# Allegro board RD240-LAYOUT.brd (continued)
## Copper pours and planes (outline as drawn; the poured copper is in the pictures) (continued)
SIG0053 on BOTTOM: 232.38,115.85 231.82,116.4 232.38,116.95 232.75,116.95 232.89,116.93 233.61,116.55 234.54,116.55 234.67,116.68 234.45,117.09 234.4,117.2 234.39,117.31 234.39,117.7 234.85,118.16 235.31,117.7 235.31,117.31 235.3,117.2 235.25,117.09 234.98,116.58 234.96,116.54 234.71,116.29 234.67,116.27 234.63,116.25 234.6,116.25 233.61,116.25 232.89,115.87 232.75,115.85
SIG0053 on BOTTOM: 236.44,115.72 236.4,115.74 236.34,115.82 236.35,115.93 236.37,115.96 236.4,115.99 236.68,116.17 237.35,116.83 237.12,117.15 237.09,117.31 237.09,118.09 237.1,118.18 237.12,118.26 237.28,118.66 237.1,119.28 237.09,119.34 237.09,120.44 237.16,120.68 237.36,120.85 237.89,121.1 238.06,121.43 238.08,121.46 238.11,121.48 238.24,121.5 238.33,121.39 238.34,121.37 238.34,121.34 238.37,121.34 238.4,121.33 238.48,121.28 238.51,121.19 238.49,121.11 238.43,121.06 238.11,120.89 238.01,120.39 238.01,119.34 238,119.28 237.82,118.66 237.98,118.26 238,118.18 238.01,118.09 238.01,117.31 237.98,117.15 237.67,116.73 237.66,116.72 236.9,115.96 236.71,115.68 236.69,115.65 236.57,115.61 236.46,115.68
SIG0053 on BOTTOM: 233.23,118.44 233.04,118.36 232.96,118.55 232.96,118.57 233.18,119.03 233.18,119.12 233.19,119.18 234.09,120.11 234.13,120.13 234.63,120.4 234.65,120.41 234.84,120.33 234.77,120.14 234.54,120.02 234.54,119.98 234.77,119.86 234.81,119.83 234.83,119.65 234.65,119.59 234.63,119.6 234.23,119.81 233.47,119.06 233.47,119.03 233.69,118.57 233.69,118.55 233.61,118.36 233.42,118.44 233.32,118.64
SIG0054 on TOP: 240.78,77.9 240.82,77.9 242.18,77.9 242.22,77.9 242.26,77.89 242.33,77.86 242.4,77.82 243.64,77.15 243.85,77.15 244.1,76.9 243.85,76.65 243.64,76.65 242.16,75.88 241.9,75.85 241.1,75.85 240.07,76.72 240.74,77.89
SIG0054 on BOTTOM: 237.38,70.15 236.82,70.7 237.38,71.25 238.03,71.25 238.17,71.23 238.72,70.95 239.07,70.95 239.39,71.11 239.49,71.15 239.6,71.16 239.85,71.16 240.31,70.7 239.85,70.24 239.6,70.24 239.49,70.25 239.39,70.29 239.07,70.45 238.72,70.45 238.17,70.17 238.03,70.15
SIG0054 on BOTTOM: 244.22,68.85 244.05,68.76 243.93,68.91 243.93,68.92 243.92,68.92 243.77,69.04 243.86,69.21 244.03,69.27 244.03,69.35 243.96,69.67 243.95,69.72 243.95,69.83 243.8,70.06 243.34,70.52 242.83,70.28 242.74,70.25 242.64,70.24 242.55,70.24 242.22,70.37 242.09,70.7 242.09,71.27 242.11,71.4 242.16,71.52 242.3,71.73 242.3,71.97 242.16,72.18 242.11,72.3 242.09,72.43 242.09,73 242.55,73.46 243.01,73 243.01,72.43 242.99,72.3 242.94,72.18 242.8,71.97 242.8,71.73 242.94,71.52 242.99,71.4 243.01,71.27 243.01,71.03 243.48,70.81 244.02,70.27 244.37,70.01 244.4,69.9 244.4,69.72 244.39,69.67 244.32,69.35 244.32,69.17 244.32,69.14 244.32,69.11
SIG54 on BOTTOM: 150.43,7.08 150.28,7.22 150.43,7.38 152.96,7.38 153.53,7.95 153.58,7.98 153.64,7.99 154.95,7.99 155.28,8.06 155.33,8.06 155.5,8.06 155.73,7.84 155.5,7.62 155.33,7.62 155.28,7.62 154.95,7.69 153.7,7.69 153.13,7.12 153.09,7.09 153.06,7.08 153.03,7.08
SIG0055 on TOP: 240.82,70.3 240.77,70.31 240.73,70.32 240.07,71.49 241.1,72.35 241.9,72.35 242.16,72.32 242.4,72.22 243.64,71.55 243.85,71.55 244.1,71.3 243.85,71.05 243.64,71.05 242.34,70.34 242.27,70.32 242.23,70.31 242.18,70.3
SIG56 on BOTTOM: 149.75,9.62 149.7,9.63 149.49,9.68 149.42,9.72 148.99,10.14 148.96,10.19 148.95,10.25 148.95,10.81 148.96,10.87 149.73,11.66 149.77,11.68 149.81,11.7 149.84,11.7 150.59,11.7 151.15,12.26 151.15,12.55 151.08,12.87 151.07,12.93 151.3,13.15 151.53,12.93 151.52,12.87 151.45,12.55 151.45,12.2 151.44,12.14 150.76,11.44 150.72,11.42 150.68,11.4 150.65,11.4 149.9,11.4 149.25,10.75 149.25,10.31 149.57,9.99 149.7,10.02 149.75,10.03 150.43,10.03 150.62,9.82 150.43,9.62
SIG82 on TOP: 158.97,124.23 158.94,124.29 158.94,124.39 158.96,124.43 159.6,125.29 159.24,125.65 157.8,125.65 157.74,125.66 157.69,125.69 155.29,128.09 155.26,128.14 155.25,128.2 155.25,129.12 154.98,129.39 154.37,129.39 154.31,129.4 154.27,129.43 154.05,129.65 154.02,129.69 154.01,129.75 154.01,132.17 154.02,132.23 154.05,132.27 154.33,132.55 154.37,132.58 154.43,132.59 156.41,132.59 156.47,132.58 156.51,132.55 156.77,132.29 156.8,132.25 156.81,132.19 156.81,129.69 156.8,129.63 156.77,129.59 156.61,129.43 156.57,129.4 156.51,129.39 155.81,129.39 155.55,129.13 155.55,128.26 157.86,125.95 159.3,125.95 159.36,125.94 159.91,125.41 159.92,125.39 160.64,124.43 160.66,124.39 160.66,124.29 160.63,124.23 160.57,124.2 160.52,124.19 160.45,124.21 160.4,124.25 160.07,124.69 159.53,124.69 159.2,124.25 159.15,124.21 159.08,124.19 159.03,124.2
SIG82 on BOTTOM: 159.79,123.07 159.81,123.2 159.86,123.32 160,123.53 160,123.77 159.86,123.98 159.81,124.1 159.79,124.23 159.79,124.38 159.21,124.65 158.88,124.65 158.82,124.66 158.77,124.69 158.76,124.7 158.53,124.85 158.45,124.85 158.4,124.86 158.08,124.92 157.59,124.92 157.53,124.94 157.48,124.97 155.29,127.15 155.26,127.2 155.25,127.26 155.25,129.11 154.97,129.39 154.64,129.39 154.58,129.4 154.54,129.43 154.05,129.92 154.02,129.96 154.01,130.02 154.01,132.17 154.02,132.23 154.05,132.27 154.33,132.55 154.37,132.58 154.43,132.59 156.41,132.59 156.47,132.58 156.51,132.55 156.77,132.29 156.8,132.25 156.81,132.19 156.81,129.97 156.8,129.91 156.77,129.87 156.33,129.43 156.29,129.4 156.23,129.39 155.83,129.39 155.55,129.11 155.55,127.32 157.65,125.22 158.08,125.22 158.4,125.29 158.45,125.3 158.6,125.3 158.71,125.27 158.79,125.2 158.95,124.95 159.21,124.95 159.89,125.25 159.98,125.26 160.25,125.26 160.58,125.13 160.71,124.8 160.71,124.23 160.69,124.1 160.64,123.98 160.5,123.77 160.5,123.53 160.64,123.32 160.69,123.2 160.71,123.07 160.71,122.5 160.25,122.04 159.79,122.5
SIG82 on BOTTOM: 164.83,121.95 164.7,121.97 164.11,122.25 163.77,122.25 163.31,122.05 163.22,122.04 162.95,122.04 162.49,122.5 162.95,122.96 163.22,122.96 163.31,122.95 163.77,122.75 164.11,122.75 164.7,123.03 164.83,123.05 165.55,123.05 166.1,122.5 165.55,121.95
SIG86 on BOTTOM: 137.98,5.16 137.84,5.17 137.7,5.23 137.36,5.4 137.29,5.47 137.26,5.52 137.25,5.57 137.25,5.96 137.27,6.03 137.33,6.09 137.7,6.29 137.84,6.34 137.98,6.36 138.3,6.36 138.44,6.34 139.3,5.91 139.33,5.91 139.63,6.21 139.66,6.23 140.48,6.63 140.61,6.65 140.8,6.65 140.93,6.63 141.05,6.59 141.72,6.25 141.91,6.25 142.13,6.47 142.39,6.82 142.5,6.85 142.68,6.85 142.73,6.84 143.03,6.78 143.04,6.78 143.64,7.38 143.69,7.41 143.75,7.42 144.57,7.42 144.78,7.22 144.57,7.03 143.71,7.03 143.21,6.52 143.16,6.49 143.1,6.47 143.03,6.47 142.73,6.41 142.68,6.4 142.57,6.4 142.34,6.25 142.08,5.99 142.03,5.96 141.97,5.95 141.72,5.95 141.05,5.61 140.93,5.57 140.8,5.55 140.61,5.55 140.48,5.57 139.85,5.87 139.72,5.87 139.49,5.65 139.45,5.62 139.39,5.61 139.3,5.61 138.44,5.17 138.3,5.16
SIG91 on TOP: outline of 82 points within 163.75,70.7 171.89,74.15
SIG95 on TOP: 150.96,107.25 150.51,107.7 150.96,108.15 151.21,108.15 151.31,108.14 151.41,108.1 151.92,107.85 152.04,107.85 152.79,108.6 152.96,108.93 152.98,108.96 153.01,108.98 153.14,109 153.23,108.89 153.24,108.87 153.24,108.84 153.26,108.84 153.4,108.72 153.33,108.56 153,108.39 152.21,107.59 152.17,107.57 152.13,107.55 152.1,107.55 151.92,107.55 151.41,107.3 151.31,107.26 151.21,107.25
SIG95 on TOP: 146.55,103.25 146.39,103.32 146.32,103.47 146.32,104.21 146.1,104.9 146.09,104.98 146.09,105.79 146.1,105.89 146.13,105.98 146.31,106.36 146.12,106.89 146.1,106.97 146.09,107.05 146.09,108.39 146.1,108.47 146.11,108.54 146.3,109.12 146.3,109.58 146.31,109.63 146.38,109.93 146.38,110 146.1,110.43 146.09,110.57 146.19,110.66 146.27,110.66 146.33,110.62 146.35,110.59 146.48,110.4 146.48,110.4 146.55,110.62 146.57,110.65 146.6,110.68 146.68,110.72 146.76,110.71 146.83,110.63 146.84,110.54 146.84,110.53 146.68,110.02 146.68,109.93 147.05,109.55 148.04,109.55 148.09,109.54 148.14,109.51 148.34,109.31 148.37,109.27 148.67,108.66 148.69,108.55 148.69,107.7 148.24,107.25 147.79,107.7 147.79,108.55 147.8,108.66 148.01,109.08 148.01,109.16 147.92,109.25 147,109.25 146.82,109.07 146.82,108.96 147,108.48 147.01,108.39 147.01,107.05 147,106.97 146.98,106.89 146.79,106.36 146.97,105.98 147,105.89 147.01,105.79 147.01,104.98 147,104.9 146.99,104.83 146.78,104.21 146.78,103.84 146.81,103.81 146.86,103.73 146.88,103.65 146.88,103.47 146.81,103.32 146.65,103.25
SIG95 on BOTTOM: 152.79,109 152.34,109.44 152.31,109.49 152.3,109.55 152.3,113.3 152.31,113.36 152.34,113.41 156.25,117.31 156.25,121.31 155.95,121.93 155.91,122.05 155.9,122.17 155.9,122.9 156.45,123.45 157,122.9 157,122.17 156.98,122.01 156.91,121.87 156.55,121.3 156.55,117.25 156.54,117.19 156.51,117.14 152.6,113.24 152.6,109.61 153,109.21 153.33,109.04 153.36,109.02 153.38,108.99 153.4,108.86 153.29,108.77 153.27,108.76 153.24,108.76 153.24,108.74 153.12,108.6 152.96,108.67
SIG104 on TOP: 146.55,48.21 146.46,48.3 146.45,48.33 146.38,48.48 146.1,49.11 146.09,49.21 146.09,52.28 146.08,52.78 145.92,52.94 145.87,53.01 145.85,53.1 145.85,53.38 143.8,53.38 143.71,53.39 143.64,53.44 143.18,53.91 143.13,53.98 143.11,54.06 143.11,54.21 143.06,54.6 143.06,54.63 143.06,55.26 143.34,55.53 143.61,55.26 143.61,54.63 143.61,54.6 143.56,54.21 143.56,54.16 143.89,53.83 146.07,53.83 146.23,53.76 146.3,53.6 146.3,53.19 146.46,53.03 146.48,53.01 146.5,52.98 146.97,52.47 147.01,52.29 147.01,48.8 147,48.74 146.97,48.7 146.92,48.65 146.92,48.24 146.99,47.89 147,47.84 147,47.7 146.78,47.48 146.55,47.7
SIG115 on TOP (solid shape): 224.11,80.66 224.65,80.3 225.03,79.74 225.15,79.1 225.01,78.44 224.65,77.9 224.09,77.52 223.45,77.4 217.55,77.4 216.89,77.54 216.35,77.9 215.97,78.46 215.85,79.1 215.99,79.76 216.35,80.3 216.91,80.68 217.55,80.8 223.45,80.8
SIG115 on BOTTOM (solid shape): 224.11,80.66 224.65,80.3 225.03,79.74 225.15,79.1 225.01,78.44 224.65,77.9 224.09,77.52 223.45,77.4 217.55,77.4 216.89,77.54 216.35,77.9 215.97,78.46 215.85,79.1 215.99,79.76 216.35,80.3 216.91,80.68 217.55,80.8 223.45,80.8
SIG115 on TOP: 219.01,68.2 218.95,68.21 218.91,68.24 216.48,70.67 216.45,70.72 216.44,70.77 216.44,77.36 216.34,77.43 216.23,77.45 216.1,77.45 215.99,77.49 215.95,77.6 215.95,80.5 215.99,80.65 216.1,80.76 216.25,80.8 224.85,80.8 225,80.76 225.11,80.65 225.15,80.5 225.15,77.45 225.19,77.3 225.24,77.24 226.95,75.53 231.75,75.53 231.86,75.48 231.9,75.38 231.9,71.25 231.86,71.14 231.75,71.1 227.47,71.1 226.59,70.22 226.59,68.82 226.58,68.76 226.55,68.72 226.07,68.24 226.03,68.21 225.97,68.2
SIG115 on BOTTOM: 232.26,51.93 232.2,51.94 232.16,51.97 229.94,54.19 226.61,54.19 226.56,54.2 226.51,54.23 225.79,54.95 225.76,54.99 225.75,55.05 225.75,65.55 222.64,68.66 217.86,68.66 217.8,68.68 217.76,68.71 216.29,70.17 216.26,70.22 216.25,70.28 216.25,77.3 216.22,77.37 216.15,77.4 216,77.4 215.89,77.44 215.85,77.55 215.85,80.5 215.85,80.51 215.94,80.71 216.14,80.8 224.75,80.8 224.9,80.76 225.01,80.65 225.05,80.5 225.05,74.1 226.62,72.53 227.25,72.53 227.31,72.52 227.35,72.49 227.65,72.19 227.68,72.15 227.69,72.09 227.69,69.71 228.61,68.79 228.66,68.73 228.7,68.58 228.7,66.42 228.74,66.27 228.79,66.21 229.1,65.9 231.75,65.9 231.86,65.86 231.9,65.75 231.9,54.76 232.71,53.95 236.1,53.95 236.21,53.91 236.25,53.8 236.25,52.08 236.21,51.97 236.1,51.93
SIG116 on TOP: 230.66,63.66 230.66,63.71 230.79,64.08 230.81,64.11 230.83,64.14 232.8,66.11 232.8,66.16 232.69,66.52 232.75,66.69 232.94,66.67 232.95,66.65 232.96,66.67 233.15,66.69 233.21,66.52 233.1,66.16 233.1,66.05 233.09,65.99 231.11,64 231.21,63.71 231.21,63.66 231.21,63.04 230.94,62.77 230.66,63.04
SIG116 on TOP: 233.24,47.89 233.35,48.27 233.35,48.39 232.84,48.9 232.2,48.9 232.09,48.94 232.05,49.05 232.05,49.59 232.1,49.7 232.21,49.74 232.21,49.76 232.32,49.9 232.49,49.83 232.68,49.48 233.64,48.51 233.65,48.45 233.65,48.27 233.76,47.89 233.77,47.82 233.74,47.76 233.66,47.7 233.55,47.71 233.52,47.73 233.5,47.76 233.49,47.74 233.46,47.72 233.43,47.7 233.29,47.72 233.23,47.85
SIG116 on BOTTOM: 228,44.5 227.9,44.54 227.85,44.65 227.85,45.53 227.9,45.64 228,45.68 228.4,45.68 228.51,45.64 228.55,45.53 228.55,45.42 228.82,45.15 229.39,45.15 229.98,45.39 230.06,45.4 230.3,45.4 230.7,45 230.3,44.6 230.06,44.6 229.98,44.61 229.39,44.85 228.8,44.85 228.55,44.6 228.5,44.53 228.41,44.5
SIG117 on TOP: 227.84,63.67 227.86,63.76 227.88,63.85 228.08,64.26 227.24,65.09 227.21,65.14 227.2,65.2 227.2,69.05 227.21,69.11 227.74,69.66 227.78,69.68 227.82,69.7 227.85,69.7 228.51,69.7 228.87,69.81 229.04,69.75 229.02,69.56 229,69.55 229.02,69.54 229.04,69.35 228.87,69.29 228.51,69.4 227.91,69.4 227.5,68.99 227.5,65.26 228.36,64.4 228.38,64.38 228.39,64.36 228.63,63.85 228.66,63.76 228.67,63.67 228.67,63.04 228.26,62.63 227.84,63.04
SIG117 on BOTTOM: 229.7,68.65 229.64,68.66 229.59,68.69 229.15,69.14 228.82,69.31 228.79,69.33 228.77,69.36 228.75,69.49 228.86,69.58 228.88,69.59 228.91,69.59 228.91,69.61 229.03,69.75 229.19,69.68 229.36,69.35 229.76,68.95 232.77,68.95 233.4,69.58 233.4,70.07 233.29,70.42 233.28,70.47 233.28,70.51 233.28,70.7 233.36,70.89 233.55,70.97 234.08,70.97 234.12,70.97 234.16,70.96 234.51,70.85 234.97,71.06 235,71.07 235.01,71.1 235.22,71.57 235.22,72.42 235.24,72.48 235.29,72.55 235.41,73.12 235.61,73.43 235.95,73.55 236.32,73.55 236.88,73 236.32,72.45 236.01,72.45 235.53,72.35 235.53,71.57 235.74,71.1 235.77,71.02 235.78,70.93 235.78,70.7 235.66,70.42 235.38,70.3 235.14,70.3 235.06,70.31 234.97,70.34 234.51,70.55 234.16,70.44 234.12,70.43 234.08,70.42 233.81,70.42 233.7,70.07 233.7,69.52 233.69,69.46 232.93,68.69 232.9,68.67 232.86,68.65 232.83,68.65
SIG121 on TOP: 228.74,56.85 228.18,56.85 228.08,56.87 228,56.92 227.82,57.1 227.82,57.45 228.18,57.45 228.28,57.35 228.74,57.35 229.19,57.48 229.19,57.69 229.2,57.79 229.23,57.88 229.41,58.26 229.22,58.79 229.2,58.87 229.19,58.95 229.19,60.29 229.2,60.38 229.45,61.03 229.45,61.3 229.68,61.52 229.9,61.3 229.9,61.02 230.09,60.44 230.1,60.37 230.11,60.29 230.11,58.95 230.1,58.87 230.08,58.79 229.89,58.26 230.07,57.88 230.1,57.79 230.11,57.69 230.11,57.3 229.99,56.99 229.7,56.84 229.58,56.68 229.38,56.66
SIG126 on TOP: 233.14,102.89 232.95,102.87 232.89,103.04 232.98,103.26 232.44,103.8 231.54,103.79 231.27,104.06 231.54,104.34 232.16,104.34 232.26,104.32 232.34,104.27 232.56,104.09 232.61,104.06 233.26,103.41 233.28,103.38 233.29,103.35 233.41,103.04 233.35,102.87 233.16,102.89 233.15,102.9
SIG127 on TOP: 232.95,104.94 232.95,106.39 232.75,106.59 232.68,106.59 232.2,106.37 232.12,106.34 232.03,106.33 231.54,106.33 231.13,106.74 231.54,107.16 232.03,107.16 232.12,107.14 232.2,107.12 232.68,106.89 232.81,106.89 232.86,106.88 232.91,106.85 233.24,106.51 233.25,106.45 233.25,104.94 233.36,104.58 233.3,104.41 233.11,104.43 233.1,104.45 233.09,104.43 232.9,104.41 232.84,104.58
SIG127 on BOTTOM: 231.7,114.04 231.7,114.19 230.27,115.62 230.25,115.64 230.24,115.66 230.01,116.16 229.98,116.24 229.97,116.33 229.97,116.4 229.98,116.48 230.22,117.03 230.22,118.96 229.84,119.34 229.81,119.39 229.8,119.45 229.8,120.57 229.69,120.92 229.68,120.97 229.68,121.01 229.68,121.2 229.95,121.47 230.22,121.2 230.22,121.01 230.22,120.97 230.21,120.92 230.1,120.57 230.1,119.51 230.37,119.24 230.83,118.95 231.32,118.95 231.88,118.4 231.32,117.85 231.02,117.85 230.53,117.73 230.53,117.03 230.77,116.48 230.78,116.4 230.78,116.33 230.77,116.24 230.74,116.16 230.55,115.76 231.99,114.31 232,114.25 232,114.04 232.11,113.68 232.05,113.51 231.86,113.53 231.85,113.55 231.84,113.53 231.65,113.51 231.59,113.68
SIG134 on TOP (solid shape): 224.11,118.56 224.65,118.2 225.03,117.64 225.15,117 225.01,116.34 224.65,115.8 224.09,115.42 223.45,115.3 217.55,115.3 216.89,115.44 216.35,115.8 215.97,116.36 215.85,117 215.99,117.66 216.35,118.2 216.91,118.58 217.55,118.7 223.45,118.7
SIG134 on BOTTOM (solid shape): 224.11,118.56 224.65,118.2 225.03,117.64 225.15,117 225.01,116.34 224.65,115.8 224.09,115.42 223.45,115.3 217.55,115.3 216.89,115.44 216.35,115.8 215.97,116.36 215.85,117 215.99,117.66 216.35,118.2 216.91,118.58 217.55,118.7 223.45,118.7
SIG134 on BOTTOM: 226.23,105.1 226.17,105.11 226.12,105.14 224.61,106.65 224.42,106.78 224.2,106.83 220.69,106.83 220.63,106.84 220.58,106.87 216.29,111.16 216.26,111.2 216.25,111.26 216.25,118.4 216.29,118.55 216.4,118.66 216.55,118.7 225.81,118.7 225.87,118.69 225.91,118.66 226.09,118.48 226.12,118.43 226.13,118.37 226.13,113.11 226.35,112.9 231.75,112.9 231.86,112.86 231.9,112.75 231.9,108.62 231.86,108.52 231.75,108.47 229.75,108.47 228.82,107.55 228.82,105.25 228.78,105.14 228.68,105.1
SIG135 on TOP (solid shape): 224.11,123.56 224.65,123.2 225.03,122.64 225.15,122 225.01,121.34 224.65,120.8 224.09,120.42 223.45,120.3 217.55,120.3 216.89,120.44 216.35,120.8 215.97,121.36 215.85,122 215.99,122.66 216.35,123.2 216.91,123.58 217.55,123.7 223.45,123.7
SIG135 on BOTTOM (solid shape): 224.11,123.56 224.65,123.2 225.03,122.64 225.15,122 225.01,121.34 224.65,120.8 224.09,120.42 223.45,120.3 217.55,120.3 216.89,120.44 216.35,120.8 215.97,121.36 215.85,122 215.99,122.66 216.35,123.2 216.91,123.58 217.55,123.7 223.45,123.7
SIG135 on TOP: 216.15,121.15 215.94,121.24 215.85,121.44 215.85,121.45 215.85,123.55 215.89,123.66 216,123.7 216.15,123.7 216.22,123.73 216.25,123.8 216.25,127.75 216.25,127.76 216.26,127.83 216.29,127.89 218.46,130.06 218.5,130.09 218.56,130.1 222.05,130.1 223.51,131.56 223.55,131.59 223.61,131.6 231.75,131.6 231.86,131.56 231.9,131.45 231.9,127.33 231.86,127.22 231.75,127.17 229.82,127.17 229.77,127.15 229.75,127.1 229.75,125.7 229.77,125.65 229.82,125.62 231.75,125.62 231.86,125.58 231.9,125.47 231.9,121.3 231.86,121.19 231.75,121.15 231.28,121.15 231.24,121.15 231.18,121.17 229.82,121.17 229.76,121.15 229.72,121.15
SIG135 on BOTTOM: 216.55,120.3 216.4,120.34 216.29,120.45 216.25,120.6 216.25,127.73 216.26,127.8 216.34,127.94 219.96,131.56 220,131.59 220.06,131.6 231.75,131.6 231.86,131.56 231.9,131.45 231.9,127.35 231.86,127.24 231.75,127.2 229.45,127.2 228.8,126.55 228.8,123.75 228.76,123.64 228.65,123.6 225.5,123.6 225.05,123.15 225.05,120.6 225.01,120.45 224.9,120.34 224.75,120.3
SIG138 on BOTTOM: 240.4,105.1 240.29,105.14 240.25,105.25 240.25,106.69 240.26,106.75 240.29,106.79 241.2,107.7 241.2,121.2 240.97,121.43 240.94,121.47 240.93,121.53 240.93,123.03 240.94,123.09 240.97,123.13 241.2,123.36 241.2,127.19 241.21,127.25 241.24,127.29 245.06,131.11 245.1,131.14 245.16,131.15 247.6,131.15 247.71,131.11 247.75,131 247.75,124.68 247.74,124.62 247.71,124.58 245.75,122.62 245.75,106.01 245.74,105.95 245.71,105.91 244.94,105.14 244.9,105.11 244.84,105.1
SIG138 on BOTTOM: 232.35,105.1 232.24,105.14 232.2,105.25 232.2,106.95 232.24,107.06 232.35,107.1 237.45,107.1 237.56,107.06 237.6,106.95 237.6,105.25 237.56,105.14 237.45,105.1 235.49,105.1 235.38,105.12 235.3,105.12 234.3,105.12 234.22,105.12 234.11,105.1
SIG138 on BOTTOM: 232.35,123.6 232.24,123.64 232.2,123.75 232.2,125.45 232.24,125.56 232.35,125.6 235.3,125.6 235.41,125.56 235.45,125.45 235.45,123.75 235.41,123.64 235.3,123.6
SIG138 on CONDUCTIVE3: 222,125.5 221.96,125.51 221.93,125.53 218.66,128.8 207.2,128.8 207.16,128.81 207.13,128.83 206.79,129.17 206.4,129.29 206.34,129.42 206.46,129.48 206.64,129.42 206.68,129.46 206.62,129.64 206.61,129.67 206.69,129.77 206.8,129.71 206.81,129.7 206.93,129.31 207.24,129 218.7,129 218.74,128.99 218.77,128.97 222.04,125.7 242.25,125.7 242.4,125.85 242.4,126.7 242.5,126.8 242.6,126.7 242.6,126.18 243.08,125.7 243.6,125.7 243.7,125.6 243.6,125.5
SIG148 on TOP: 254.75,11.21 254.66,11.3 253.15,11.3 253.09,11.31 253.04,11.34 252.59,11.79 252.58,11.82 252.56,11.84 252.45,12.09 252.44,12.13 252.44,12.18 252.49,12.27 252.59,12.3 252.65,12.28 252.7,12.25 252.75,12.28 252.81,12.3 252.89,12.27 252.96,12.19 252.95,12.09 252.88,11.93 253.21,11.6 254.46,11.6 254.6,11.74 254.79,12.02 255.04,12.12 255.2,11.9 255.2,9.9 254.97,9.68 254.75,9.9
SIG149 on TOP: 253.66,12.13 253.66,12.16 253.63,12.16 253.6,12.17 253.52,12.22 253.49,12.31 253.51,12.39 253.57,12.44 253.9,12.61 254.81,13.52 254.76,13.79 254.75,13.84 254.75,15.8 254.97,16.02 255.2,15.8 255.2,13.84 255.19,13.79 255.11,13.4 254.11,12.4 253.94,12.07 253.92,12.04 253.89,12.02 253.76,12 253.67,12.11
SIG150 on TOP: 254.75,7.64 254.54,7.85 253.6,7.85 253.54,7.86 253.49,7.89 252.59,8.79 252.56,8.84 252.55,8.9 252.55,10.36 252.44,10.72 252.43,10.79 252.47,10.86 252.5,10.89 252.53,10.9 252.58,10.91 252.65,10.9 252.7,10.85 252.75,10.9 252.82,10.91 252.9,10.89 252.96,10.81 252.96,10.72 252.85,10.36 252.85,8.96 253.66,8.15 254.42,8.15 254.75,8.22 254.8,8.22 254.97,8.22 255.13,8.16 255.2,8 255.2,6.1 254.97,5.88 254.75,6.1
SIG150 on BOTTOM: 252.66,10.73 252.66,10.76 252.63,10.76 252.6,10.77 252.52,10.82 252.49,10.91 252.51,10.99 252.57,11.04 252.9,11.21 253.22,11.53 253.27,11.56 253.32,11.57 253.84,11.57 253.89,11.63 253.94,11.66 253.99,11.67 254.27,11.72 254.3,11.72 255.06,11.72 255.26,11.53 255.06,11.32 254.37,11.32 254.35,11.33 254.01,11.33 254.01,11.32 253.96,11.29 253.9,11.28 253.39,11.28 253.11,11 252.94,10.67 252.92,10.64 252.89,10.62 252.76,10.6 252.67,10.71
SIG151 on BOTTOM: 253.47,7.25 253.48,7.3 253.55,7.63 253.56,10.46 254.07,10.98 254.11,11.01 254.15,11.02 254.47,11.07 255.06,11.07 255.26,10.88 255.06,10.68 254.47,10.68 254.23,10.71 253.85,10.34 253.85,7.63 253.92,7.3 253.93,7.25 253.93,7.12 253.7,6.9 253.47,7.12
SIG152 on TOP: 252.44,13.58 252.55,13.94 252.55,14.3 252.56,14.36 252.59,14.41 253.55,15.36 253.55,16.42 253.56,16.48 253.59,16.53 254.6,17.54 254.79,17.82 254.81,17.85 254.93,17.89 255.04,17.82 255.06,17.78 255.1,17.76 255.16,17.68 255.15,17.57 255.13,17.54 255.1,17.51 254.82,17.33 253.85,16.36 253.85,15.3 253.84,15.24 252.85,14.24 252.85,13.94 252.96,13.58 252.97,13.54 252.91,13.42 252.77,13.4 252.73,13.42 252.7,13.45 252.67,13.42 252.63,13.4 252.49,13.42 252.43,13.54
SIG152 on BOTTOM: 256.49,11.88 256.3,12.16 256.19,12.27 256.16,12.32 256.15,12.38 256.15,12.99 255.86,13.27 255.04,13.27 255.02,13.28 254.3,13.28 254.27,13.28 253.99,13.32 253.13,13.32 252.77,13.23 252.73,13.23 252.6,13.31 252.61,13.46 252.62,13.48 252.65,13.5 252.61,13.55 252.59,13.62 252.62,13.7 252.7,13.76 252.8,13.76 253.14,13.62 253.99,13.62 254.27,13.67 254.3,13.68 255.82,13.68 255.88,13.66 255.93,13.63 256.44,13.11 256.45,13.05 256.45,12.44 256.52,12.37 256.8,12.19 256.82,12.17 256.85,12.12 256.87,12.06 256.85,11.99 256.8,11.94 256.76,11.92 256.74,11.88 256.63,11.81 256.51,11.85
SIG156 on BOTTOM: 278.36,3.35 274,3.35 273.94,3.36 273.89,3.39 265.46,11.82 265.23,11.8 265.1,12 265.1,13.46 265.11,13.51 265.18,13.84 265.18,14.11 265.09,14.19 265.06,14.24 265.05,14.3 265.05,14.42 264.98,14.75 264.98,14.8 264.98,14.97 265.2,15.2 265.43,14.97 265.43,14.8 265.42,14.75 265.35,14.42 265.35,14.36 265.46,14.23 265.48,14.17 265.48,13.84 265.54,13.51 265.55,13.46 265.55,12.16 274.06,3.65 278.36,3.65 278.72,3.76 278.76,3.77 278.81,3.76 278.88,3.71 278.91,3.62 278.9,3.55 278.85,3.5 278.9,3.45 278.91,3.38 278.88,3.29 278.81,3.24 278.76,3.23 278.72,3.24
SIG156 on BOTTOM: outline of 98 points within 254.86,10.68 264.7,15.45
SIG156 on BOTTOM: 257.95,11.08 257.96,11.13 258.02,11.45 258.02,12.54 257.56,13 257.31,13.16 257.02,13.22 256.93,13.22 256.87,13.24 256.82,13.27 256.12,13.97 256.07,13.97 256.05,13.97 255.79,13.93 255.06,13.93 254.99,13.94 254.93,13.97 253.85,13.96 253.74,13.93 253.63,13.98 253.59,14.08 253.59,14.1 253.58,14.12 253.55,14.2 253.58,14.28 253.59,14.3 253.59,14.32 253.63,14.42 253.74,14.47 253.79,14.46 254.2,14.32 254.44,14.32 254.5,14.31 254.54,14.28 254.93,14.28 254.99,14.31 255.06,14.32 255.79,14.32 255.83,14.32 256.11,14.28 256.18,14.28 256.23,14.26 256.99,13.53 257.02,13.53 257.35,13.6 257.4,13.6 257.58,13.6 257.63,13.59 257.95,13.53 258.75,13.53 258.79,13.52 258.83,13.5 259.12,13.31 259.15,13.29 259.19,13.2 259.17,13.1 259.13,13.07 259.08,13.04 259.06,13 259.02,12.96 258.92,12.94 258.83,12.98 258.81,13 258.67,13.22 258.05,13.22 257.97,13.14 257.97,13.02 258.31,12.66 258.32,12.6 258.32,11.45 258.39,11.13 258.4,11.08 258.4,10.9 258.18,10.68 257.95,10.9
SIG183 on BOTTOM: 248.4,15.28 248.34,15.29 248.29,15.32 248.19,15.43 248.08,15.43 247.75,15.36 247.7,15.35 246.6,15.35 246.55,15.36 246.22,15.43 246.17,15.44 246.12,15.47 245.94,15.65 245.78,15.65 245.45,15.58 245.4,15.57 245.22,15.57 245,15.8 245.22,16.02 245.4,16.02 245.45,16.02 245.78,15.95 246,15.95 246.06,15.94 246.28,15.74 246.55,15.79 246.6,15.8 247.7,15.8 247.75,15.79 248.08,15.72 248.25,15.72 248.31,15.71 248.36,15.68 248.46,15.57 249.34,15.57 249.49,15.43 249.34,15.28
SIG199 on BOTTOM (solid shape): 70.39,35.1 71.1,35.59 71.81,35.1 72.44,33.35 72.65,32.76 72.56,32.08 71.95,31.76 71.52,31.89 71.24,32.25 71.21,32.34 70.99,32.34 70.96,32.25 70,31.8 69.55,32.76
SIG199 on BOTTOM: 78.36,16.8 78.3,16.81 78.26,16.84 75.74,19.36 75.71,19.4 75.7,19.46 75.7,23.1 75.74,23.21 75.85,23.25 82.65,23.25 82.76,23.21 82.8,23.1 82.8,19.56 82.79,19.5 82.76,19.46 80.14,16.84 80.1,16.81 80.04,16.8
SIG199 on BOTTOM: 86.56,6.5 86.5,6.51 86.46,6.54 86.32,6.68 86.3,6.71 86.28,6.73 86.11,7.14 85.92,7.53 85.9,7.56 85.9,7.6 85.9,13.65 85.94,13.76 86.05,13.8 90.75,13.8 90.86,13.76 90.9,13.65 90.9,6.96 90.89,6.9 90.86,6.86 90.71,6.71 90.69,6.69 90.66,6.68 90.48,6.6 90.3,6.52 90.27,6.5 90.23,6.5
SIG199 on BOTTOM: 68.65,35.79 68.66,35.85 68.69,35.89 70.46,37.66 70.5,37.69 70.56,37.7 71.64,37.7 71.7,37.69 71.74,37.66 73.65,35.75 86.45,35.75 87.41,35.56 88.22,35.02 89.27,33.97 89.27,30.43 85.73,30.43 85.41,30.75 73.19,30.75 72.87,30.43 69.92,30 68.65,32.7
SIG199 on BOTTOM: 68.46,6.5 68.4,6.51 68.36,6.54 67.84,7.06 67.81,7.1 67.8,7.16 67.8,12.85 67.84,12.96 67.95,13 72.65,13 72.76,12.96 72.8,12.85 72.8,7.78 72.8,7.74 72.78,7.71 72.53,7.23 72.32,6.73 72.3,6.71 72.28,6.68 72.14,6.54 72.1,6.51 72.04,6.5
SIG205 on TOP: 167.78,75.95 167.22,76.5 167.78,77.05 168.15,77.05 168.28,77.03 168.87,76.75 169.21,76.75 169.55,76.92 169.57,76.92 169.7,76.9 169.77,76.78 169.76,76.75 170,76.5 169.76,76.25 169.77,76.22 169.7,76.1 169.57,76.08 169.55,76.08 169.21,76.25 168.87,76.25 168.28,75.97 168.15,75.95
SIG205 on TOP: outline of 88 points within 155.47,76.04 172.91,93.39
SIG205 on BOTTOM: 170.04,86.24 169.98,86.25 169.94,86.28 169.45,86.77 169.42,86.81 169.41,86.87 169.41,89.02 169.42,89.08 169.45,89.12 169.73,89.4 169.77,89.43 169.83,89.44 171.81,89.44 171.87,89.43 171.91,89.4 172.17,89.14 172.2,89.1 172.21,89.04 172.21,86.82 172.2,86.76 172.17,86.72 171.73,86.28 171.69,86.25 171.63,86.24
SIG00817 on BOTTOM: 126.45,77.52 126.4,77.62 126.45,77.73 128.92,80.2 129.03,80.25 129.13,80.2 132.65,76.68 132.7,76.58 132.65,76.47 130.18,74 130.07,73.95 129.97,74
SIG00818 on TOP: 166.6,50.88 167.83,52.07 168.13,52.1 168.24,51.82 168.22,51.76 168.18,51.71 167.5,51.06 167.5,50.34 168.18,49.69 168.21,49.65 168.23,49.61 168.24,49.59 168.14,49.3 167.83,49.33 167.08,50.06 166.49,50.06 164.28,47.85 163.92,47.85 163.92,48.2
SIG00818 on BOTTOM: 167.4,48.06 167.29,48.1 167.25,48.21 167.25,50.7 167.29,50.81 167.4,50.85 170.9,50.85 171.01,50.81 171.05,50.7 171.05,48.21 171.01,48.1 170.9,48.06
SIG00819 on TOP: 117.7,50.55 117.6,50.57 117.52,50.62 117.07,51.07 117.02,51.15 117,51.25 117,52.89 115.65,54.97 115.71,55.3 116.04,55.28 116.07,55.24 116.61,54.41 117.89,54.41 118.43,55.24 118.46,55.28 118.79,55.3 118.85,54.97 117.5,52.89 117.5,51.35 117.8,51.05 118.28,51.05 118.53,50.8 118.28,50.55
SIG00819 on BOTTOM: 113.76,54.1 113.65,54.14 113.61,54.25 113.61,57.75 113.65,57.86 113.76,57.9 120.74,57.9 120.85,57.86 120.89,57.75 120.89,54.25 120.85,54.14 120.74,54.1
SIG00820 on TOP (solid shape): 174.19,94.62 174.26,94.84 174.48,94.91 176.19,94.62 176.77,94.52 176.92,94.44 176.98,94.28 176.89,94.09 176.68,94.03 176.24,94.11 174.99,92.86 175.07,92.42 174.87,92.13 174.58,92.33
SIG00820 on BOTTOM: 174.7,92.6 174.59,92.64 174.55,92.75 174.55,96.19 174.59,96.3 174.7,96.34 178.2,96.34 178.31,96.3 178.35,96.19 178.35,92.75 178.31,92.64 178.2,92.6
SIG00821 on BOTTOM: 182.19,21.77 182.21,21.92 182.26,22.05 182.64,22.77 182.64,22.77 182.53,22.88 182.21,22.71 181.85,22.65 180.35,22.65 180.29,22.66 180.25,22.69 179.95,22.99 179.55,22.99 179.37,22.82 179.37,22.04 179.57,21.84 179.8,21.69 179.82,21.67 179.85,21.62 179.87,21.56 179.85,21.49 179.8,21.44 179.76,21.42 179.74,21.38 179.63,21.31 179.51,21.35 179.41,21.49 179.4,21.52 179.39,21.56 178.72,21.56 178.46,21.45 178.37,21.44 178.1,21.44 177.65,21.79 177.88,22.3 178.47,22.62 178.83,22.98 178.83,23.31 178.68,23.46 178.27,23.46 177.94,23.39 177.82,23.42 177.76,23.54 177.77,23.57 177.78,23.61 177.77,23.65 177.76,23.68 177.82,23.8 177.94,23.83 178.27,23.76 178.54,23.76 178.66,23.88 178.71,23.91 178.76,23.93 179.49,23.93 180.72,24.72 181.02,24.85 181.33,24.9 181.85,24.9 182.86,24.27 182.74,23.09 182.9,22.94 182.93,22.89 182.94,22.84 182.94,22.77 183.37,21.92 183.39,21.77 183.39,21.45 182.79,20.85 182.19,21.45
SIG00821 on BOTTOM: 178.72,29.18 178.03,29.18 177.97,29.19 177.92,29.22 177.59,29.55 177.39,29.55 177.01,29.44 176.97,29.43 176.93,29.43 176.2,29.43 175.93,29.7 176.2,29.98 176.93,29.98 176.97,29.97 177.01,29.96 177.39,29.85 177.65,29.85 177.71,29.84 178.09,29.48 178.72,29.48 179.33,29.77 179.53,29.71 179.46,29.51 179.2,29.38 179.2,29.27 179.46,29.14 179.53,28.94 179.33,28.88
SIG00822 on TOP: 176.6,20 176.42,20.07 176.35,20.25 176.35,22.35 176.37,22.45 176.42,22.53 179.87,25.98 179.95,26.03 180.05,26.05 183.25,26.05 183.4,26.2 183.4,26.38 183.28,26.5 176.75,26.5 176.5,26.75 176.75,27 185,27 186.15,28.15 186.15,29.75 186.05,29.85 185,29.85 184.91,29.87 184.83,29.92 184.72,30.03 184.67,30.11 184.65,30.2 184.65,31.25 184.67,31.34 184.72,31.42 184.88,31.58 184.96,31.63 185.05,31.65 186.45,31.65 186.54,31.63 186.62,31.58 188.68,29.52 188.73,29.44 188.75,29.35 188.75,28.25 188.73,28.16 188.68,28.08 186.22,25.62 186.14,25.57 186.05,25.55 180.15,25.55 177.6,23 177.6,20.25 177.53,20.07 177.35,20
SIG00822 on BOTTOM: 180.15,15.44 180.16,15.55 180.19,15.65 180.5,16.44 180.5,17.9 178.4,20 176.6,20 176.35,20.25 176.6,20.5 178.5,20.5 178.6,20.48 178.68,20.43 180.23,18.87 182.13,18.87 182.23,18.97 182.31,19.02 182.4,19.04 182.66,19.04 182.91,18.84 182.75,18.56 182.52,18.47 182.75,18.37 182.9,18.05 182.58,17.9 182.57,17.91 181.89,18.17 181.47,18.17 181,17.7 181,16.44 181.34,15.55 181.35,15.44 181.35,15.29 180.75,14.69 180.15,15.29
SIG00826 on TOP: 231.3,15.3 231.24,15.31 231.17,15.32 231.12,15.31 231.07,15.33 230.58,15.52 230.55,15.53 230.53,15.55 229.69,16.39 229.66,16.43 229.65,16.49 229.65,17.57 229.58,17.9 229.57,17.95 229.57,18.12 229.64,18.28 229.8,18.35 229.98,18.35 230.03,18.34 230.35,18.27 231.72,18.27 232.21,18.48 232.29,18.51 232.37,18.52 232.99,18.52 233.4,18.11 232.99,17.69 232.37,17.69 232.29,17.7 232.21,17.73 231.68,17.96 230.26,17.96 229.95,17.57 229.95,16.55 230.41,16.09 230.75,16.09 230.81,16.08 230.86,16.05 230.9,16 231.12,16 231.15,16 231.17,16 231.23,16.01 231.3,16.02 231.34,16.02 231.41,16.01 231.47,16 231.95,15.81 232.11,15.81 232.16,15.86 232.2,15.89 232.26,15.9 232.4,15.9 232.46,15.89 232.5,15.86 232.55,15.81 232.65,15.81 232.88,16.04 233.09,16.04 233.09,15.82 232.82,15.55 232.77,15.52 232.72,15.51 231.95,15.51 231.47,15.32 231.41,15.31 231.34,15.3
SIG00828 on TOP: 181.53,10.7 181.48,10.67 181.29,10.69 181.16,10.83 181.15,10.87 181.15,10.91 181.15,11.05 181.06,11.11 181.01,11.2 181,11.28 181.01,11.36 181.06,11.45 181.15,11.51 181.15,11.55 181.17,11.65 181.22,11.73 181.99,12.5 182.07,12.55 182.17,12.57 182.8,12.57 182.81,12.57 184.78,12.57 184.93,12.52 185.02,12.4 185.05,12.31 185.05,12.25 185.05,12.2 185.03,12.16 185.03,11.55 185.04,11.55 185.05,11.46 185.02,11.35 184.84,11.19 184.61,11.25 183.86,12 182.84,12 182.35,11.5 182,10.66 181.76,10.51 181.53,10.68 ; 1 cut-out
SIG00828 on BOTTOM: 184.65,11.22 184.61,11.25 183.21,12.65 183.16,12.73 183.14,12.83 183.14,15.62 183.39,15.87 183.64,15.62 183.64,12.93 184.34,12.23 184.61,12.5 184.78,12.57 184.96,12.5 185.24,12.21 186.24,12.21 186.49,11.96 186.24,11.71 185.42,11.71 184.96,11.25 184.84,11.19 184.71,11.19
SIG00829 on BOTTOM: 218.79,21.01 218.6,21.05 218.44,21.16 217.59,22 216.11,22 215.01,21.77 214.96,21.76 214.91,21.75 214.51,21.95 214.42,22.38 214.44,22.44 214.47,22.5 214.44,22.56 214.42,22.62 214.51,23.05 214.91,23.24 214.96,23.24 215.01,23.23 216.11,23 217.8,23 217.99,22.96 218.15,22.85 219,22.01 222.53,22.01 223.03,21.51 222.53,21.01
SIG00831 on BOTTOM: 181.55,10.3 181.45,10.32 181.37,10.37 180.57,11.17 180.54,11.21 180.52,11.26 180.19,12.09 180.19,12.1 180.29,12.39 180.6,12.35 180.63,12.31 180.66,12.27 180.75,12.03 180.84,12.27 180.89,12.35 180.96,12.4 181.12,12.42 181.25,12.35 181.28,12.32 181.33,12.24 181.35,12.15 181.35,11.1 181.65,10.8 192.75,10.8 193.59,11.64 193.59,11.74 193.53,11.8 192.88,11.8 191.99,11.46 191.88,11.45 191.49,11.45 191.07,11.63 190.89,12.05 190.89,12.43 190.9,12.54 190.93,12.65 191.24,13.44 191.24,13.63 190.6,14.28 189.18,14.28 188.93,14.53 189.18,14.78 190.7,14.78 190.8,14.76 190.88,14.71 191.67,13.91 191.72,13.83 191.74,13.74 191.74,13.44 192.06,12.62 192.09,12.61 192.88,12.3 194.25,12.3 194.87,12.93 194.95,12.98 195.05,13 202.2,13 203.14,13.43 203.19,13.45 203.25,13.45 203.49,13.26 203.36,12.98 202.96,12.8 202.96,12.7 203.36,12.52 203.49,12.24 203.25,12.04 203.19,12.05 203.14,12.07 202.2,12.5 195.15,12.5 193.03,10.37 192.95,10.32 192.85,10.3
SIG00834 on BOTTOM: 200.99,17.46 200.68,17.33 200.53,17.64 200.54,17.66 200.64,17.89 200.4,17.79 200.38,17.78 200.07,17.93 200.2,18.25 200.98,18.59 201.82,19.43 201.9,19.48 201.99,19.5 202.2,19.5 203.14,19.93 203.19,19.95 203.25,19.95 203.49,19.76 203.36,19.48 202.96,19.3 202.96,19.2 203.36,19.02 203.49,18.74 203.25,18.54 203.19,18.55 203.14,18.57 202.2,19 202.1,19 201.33,18.24
SIGN269 on TOP: 150.73,115.59 150.69,115.6 150.65,115.61 150.3,115.72 150.24,115.73 150.19,115.76 149.99,115.96 149.96,116.01 149.95,116.07 149.95,119.65 149.12,120.48 149.09,120.52 149.08,120.55 149.07,120.58 149.07,121.21 148.86,121.67 148.83,121.76 148.82,121.84 148.82,122.13 148.83,122.22 148.86,122.3 149.07,122.77 149.07,123.4 148.91,123.57 148.58,123.65 148.28,123.65 147.72,124.2 148.28,124.75 148.65,124.75 149,124.63 149.19,124.31 149.31,123.73 149.36,123.66 149.38,123.6 149.38,122.77 149.59,122.3 149.62,122.22 149.62,122.13 149.62,121.84 149.62,121.76 149.59,121.67 149.38,121.21 149.38,120.65 150.24,119.77 150.25,119.71 150.25,116.13 150.35,116.04 150.65,116.13 150.69,116.14 150.73,116.14 151.55,116.14 151.83,115.87 151.55,115.59
SIGN273 on BOTTOM: 239.8,51.94 239.69,51.98 239.65,52.09 239.65,53.8 239.69,53.91 239.8,53.95 241.59,53.95 246.65,59.01 246.65,72.88 246.61,73.03 246.56,73.09 245.5,74.15 234.45,74.15 234.45,73.85 234.41,73.74 234.3,73.7 232.35,73.7 232.24,73.74 232.2,73.85 232.2,75.55 232.24,75.66 232.35,75.7 233.31,75.7 233.35,75.69 233.5,75.67 233.65,75.69 233.69,75.7 233.99,75.7 234.05,75.69 234.09,75.66 245.6,75.65 248.46,78.51 248.5,78.54 248.56,78.55 252.6,78.55 252.71,78.51 252.75,78.4 252.75,69.75 252.71,69.64 252.6,69.6 248.6,69.6 248.15,69.15 248.15,58.7 248.09,58.41 247.93,58.17 242.73,52.97 241.74,51.98 241.7,51.95 241.64,51.94
SIGN318 on TOP: 158.56,77.37 158.56,77.41 158.57,77.46 158.68,77.81 158.38,78.2 158.34,78.27 158.31,78.35 157.89,78.54 157.85,78.57 156.57,79.85 154.97,79.85 154.72,79.91 154.53,80.08 153.58,79.12 153.53,79.09 153.47,79.08 151.99,79.08 149.56,76.64 149.51,76.61 149.45,76.6 148.23,76.6 147.88,76.49 147.83,76.48 147.79,76.47 147.6,76.47 147.32,76.75 147.6,77.03 147.79,77.03 147.83,77.02 147.88,77.01 148.23,76.9 149.39,76.9 151.82,79.34 151.86,79.36 151.9,79.38 151.93,79.38 153.41,79.38 154.43,80.4 154.59,80.79 154.97,80.95 155.35,80.95 155.49,80.93 156.21,80.55 156.23,80.55 156.29,80.54 157.99,78.85 158.39,79.04 158.47,79.07 158.56,79.08 158.7,79.08 158.98,78.96 159.1,78.67 159.1,78.44 159.1,78.4 159.09,78.36 158.98,77.84 158.98,77.81 159.09,77.46 159.1,77.41 159.1,77.37 159.1,76.55 158.83,76.28 158.56,76.55
SIGN322 on BOTTOM: outline of 83 points within 152.94,109.81 170.28,125.35
SIGN325 on TOP: 162.37,71.77 162.37,71.81 162.38,71.86 162.5,72.19 162.53,72.25 164.81,74.53 164.81,75.69 164.83,75.75 165.22,76.16 165.35,76.5 165.35,76.71 165.36,76.79 165.6,77.38 165.6,77.94 165.29,78.25 165.26,78.29 165.25,78.35 164.89,78.55 164.6,78.55 164.54,78.56 164.49,78.59 164.09,79 163.73,79 163.38,78.89 163.33,78.88 163.29,78.88 163.1,78.88 162.82,79.15 163.1,79.42 163.29,79.42 163.33,79.42 163.38,79.41 163.73,79.3 164.15,79.3 164.21,79.29 164.66,78.85 164.89,78.85 165.61,79.23 165.75,79.25 166.12,79.25 166.51,79.09 166.68,78.7 166.68,78.42 166.62,78.17 166.45,77.97 165.9,77.57 165.9,77.38 166.14,76.79 166.15,76.71 166.15,76.5 166.1,76.32 165.95,76.14 165.91,76.12 165.43,75.95 165.12,75.63 165.12,74.47 165.1,74.41 165.07,74.36 162.91,72.2 162.91,70.95 162.64,70.67 162.37,70.95
SIGN355 on TOP: 141.91,129.39 141.85,129.4 141.81,129.43 141.59,129.65 141.56,129.69 141.55,129.75 141.55,132.17 141.56,132.23 141.59,132.27 141.87,132.55 141.91,132.58 141.97,132.59 143.95,132.59 144.01,132.58 144.05,132.55 144.31,132.29 144.34,132.25 144.35,132.19 144.35,129.69 144.34,129.63 144.31,129.59 144.15,129.43 144.11,129.4 144.05,129.39
SIGN355 on TOP: 147.2,86.24 147.14,86.25 147.1,86.28 146.61,86.77 146.58,86.81 146.57,86.87 146.57,89.02 146.58,89.08 146.61,89.12 146.89,89.4 146.93,89.43 146.99,89.44 148.97,89.44 149.03,89.43 149.07,89.4 149.33,89.14 149.36,89.1 149.37,89.04 149.37,86.82 149.36,86.76 149.33,86.72 148.89,86.28 148.85,86.25 148.79,86.24
SIGN355 on BOTTOM: 150,98.9 149.5,99.4 150,99.9 156.99,99.9 158.45,101.35 158.61,101.46 158.8,101.5 160.66,101.5 160.69,101.54 160.73,101.58 160.79,101.64 161.23,101.78 161.6,101.5 162.05,101 161.6,100.5 161.23,100.22 160.79,100.36 160.73,100.42 160.69,100.46 160.66,100.5 159.01,100.5 157.55,99.05 157.39,98.94 157.2,98.9
SIGN355 on BOTTOM: 183.03,42.92 182.46,43.03 181.97,43.36 176.09,49.24 175.76,49.73 175.65,50.3 175.65,57.51 170.09,63.07 169.76,63.55 169.65,64.13 169.65,76.36 167.1,78.91 156.96,78.91 156.39,79.03 155.9,79.35 154.84,80.41 151.09,80.41 150.51,80.53 150.02,80.85 146.89,83.99 146.56,84.47 146.45,85.05 146.45,102.65 147.95,104.15 149.45,102.65 149.45,85.67 151.71,83.41 155.46,83.41 156.04,83.3 156.52,82.97 157.59,81.91 167.72,81.91 168.3,81.8 168.78,81.47 172.21,78.04 172.54,77.56 172.65,76.98 172.65,64.75 178.21,59.19 178.54,58.7 178.65,58.13 178.65,50.92 183.65,45.92 196.09,45.92 197.59,44.42 196.09,42.92
SIGN356 on BOTTOM: 216.92,29.44 216.86,29.44 216.79,29.46 216.15,29.65 215.69,29.65 215.59,29.67 215.51,29.72 214.98,30.25 213.56,30.66 213.55,30.66 213.39,30.98 213.7,31.14 214.31,30.96 214.62,31.27 214.44,31.88 214.61,32.19 214.92,32.03 214.92,32.02 215.33,30.6 215.79,30.15 216.15,30.15 216.86,30.35 216.92,30.36 218.36,30.36 218.43,30.35 218.49,30.34 219.13,30.15 220.53,30.15 220.78,29.9 220.53,29.65 219.13,29.65 218.49,29.46 218.43,29.44 218.36,29.44
SIGN360 on TOP (solid shape): 224.11,65.66 224.65,65.3 225.03,64.74 225.15,64.1 225.01,63.44 224.65,62.9 224.09,62.52 223.45,62.4 217.55,62.4 216.89,62.54 216.35,62.9 215.97,63.46 215.85,64.1 215.99,64.76 216.35,65.3 216.91,65.68 217.55,65.8 223.45,65.8
SIGN360 on TOP (solid shape): 224.11,60.66 224.65,60.3 225.03,59.74 225.15,59.1 225.01,58.44 224.65,57.9 224.09,57.52 223.45,57.4 217.55,57.4 216.89,57.54 216.35,57.9 215.97,58.46 215.85,59.1 215.99,59.76 216.35,60.3 216.91,60.68 217.55,60.8 223.45,60.8
SIGN360 on BOTTOM (solid shape): 224.11,65.66 224.65,65.3 225.03,64.74 225.15,64.1 225.01,63.44 224.65,62.9 224.09,62.52 223.45,62.4 217.55,62.4 216.89,62.54 216.35,62.9 215.97,63.46 215.85,64.1 215.99,64.76 216.35,65.3 216.91,65.68 217.55,65.8 223.45,65.8
SIGN360 on BOTTOM (solid shape): 224.11,60.66 224.65,60.3 225.03,59.74 225.15,59.1 225.01,58.44 224.65,57.9 224.09,57.52 223.45,57.4 217.55,57.4 216.89,57.54 216.35,57.9 215.97,58.46 215.85,59.1 215.99,59.76 216.35,60.3 216.91,60.68 217.55,60.8 223.45,60.8
SIGN360 on TOP: 217.96,40.59 217.93,40.63 217.92,40.69 217.92,45.98 216.34,47.56 216.29,47.62 216.25,47.77 216.25,65.5 216.29,65.65 216.4,65.76 216.55,65.8 224.75,65.8 224.9,65.76 225.01,65.65 225.05,65.5 225.05,60.07 226.73,58.39 226.76,58.35 226.77,58.29 226.77,56.76 228.25,55.28 228.28,55.23 228.29,55.17 228.29,50.56 232.09,46.77 243.63,46.77 243.69,46.76 243.73,46.73 245.42,45.04 245.45,45 245.46,44.94 245.46,32.22 245.45,32.16 245.42,32.12 243.84,30.54 243.8,30.51 243.74,30.5 228.11,30.5 228.05,30.51 228.01,30.54 ; 2 cut-outs
SIGN360 on BOTTOM: 233.83,27.92 233.77,27.93 233.73,27.96 229.03,32.66 219.93,32.66 219.87,32.67 219.83,32.7 219,33.53 218.97,33.58 218.96,33.64 218.96,37.66 217.03,39.59 217,39.64 216.99,39.69 216.99,55.65 216.25,56.39 216.02,56.39 215.91,56.43 215.87,56.54 215.87,64.2 215.88,64.26 215.91,64.3 216.87,65.26 216.91,65.29 216.97,65.3 223.94,65.3 224,65.29 224.04,65.26 225.12,64.18 225.15,64.14 225.16,64.08 225.16,44.95 226.18,43.93 244.13,43.93 244.19,43.92 244.23,43.89 245.38,42.74 245.41,42.7 245.42,42.64 245.42,30.12 245.41,30.06 245.38,30.02 243.32,27.96 243.28,27.93 243.22,27.92
SIGN361 on TOP (solid shape): 224.11,85.66 224.65,85.3 225.03,84.74 225.15,84.1 225.01,83.44 224.65,82.9 224.09,82.52 223.45,82.4 217.55,82.4 216.89,82.54 216.35,82.9 215.97,83.46 215.85,84.1 215.99,84.76 216.35,85.3 216.91,85.68 217.55,85.8 223.45,85.8
SIGN361 on BOTTOM (solid shape): 224.11,85.66 224.65,85.3 225.03,84.74 225.15,84.1 225.01,83.44 224.65,82.9 224.09,82.52 223.45,82.4 217.55,82.4 216.89,82.54 216.35,82.9 215.97,83.46 215.85,84.1 215.99,84.76 216.35,85.3 216.91,85.68 217.55,85.8 223.45,85.8
SIGN361 on TOP: 226.51,77.1 226.45,77.11 226.41,77.14 225.74,77.81 225.69,77.87 225.65,78.02 225.65,81.03 225.61,81.18 225.56,81.24 224.49,82.31 224.35,82.39 224.28,82.4 216,82.4 215.89,82.44 215.85,82.55 215.85,85.65 215.89,85.76 216,85.8 216.15,85.8 216.22,85.83 216.25,85.9 216.25,86.29 216.26,86.35 216.29,86.39 216.99,87.09 217.04,87.12 217.1,87.14 226.73,87.14 226.79,87.12 226.83,87.09 230.7,83.23 230.73,83.18 230.74,83.12 230.74,82.14 231.35,81.53 231.6,81.53 231.75,81.48 231.86,81.38 231.9,81.22 231.9,77.4 231.86,77.25 231.75,77.14 231.6,77.1
SIGN361 on BOTTOM: 227.82,73.7 227.75,73.71 227.61,73.79 227.04,74.36 226.99,74.42 226.95,74.57 226.95,80.33 226.91,80.48 226.86,80.54 225,82.4 216.14,82.4 215.94,82.49 215.85,82.69 215.85,82.7 215.85,85.65 215.89,85.76 216,85.8 216.15,85.8 216.22,85.83 216.25,85.9 216.25,91.78 216.26,91.85 216.34,91.99 217.66,93.31 217.72,93.36 217.87,93.4 224.1,93.4 224.25,93.36 224.36,93.25 224.4,93.1 224.4,87.94 224.96,87.38 226.62,87.38 226.69,87.36 226.83,87.29 230.57,83.54 230.6,83.5 230.62,83.44 230.62,82.02 231.11,81.53 231.6,81.53 231.75,81.48 231.86,81.38 231.9,81.22 231.9,77.35 231.86,77.2 231.75,77.09 231.6,77.05 231.28,77.05 231.24,77.05 231.18,77.08 229.82,77.08 229.76,77.05 229.72,77.05 229.5,77.05 228.89,76.44 228.81,76.3 228.8,76.23 228.8,74 228.76,73.85 228.65,73.74 228.5,73.7
SIGN362 on TOP (solid shape): 224.11,103.56 224.65,103.2 225.03,102.64 225.15,102 225.01,101.34 224.65,100.8 224.09,100.42 223.45,100.3 217.55,100.3 216.89,100.44 216.35,100.8 215.97,101.36 215.85,102 215.99,102.66 216.35,103.2 216.91,103.58 217.55,103.7 223.45,103.7
SIGN362 on TOP (solid shape): 224.11,98.56 224.65,98.2 225.03,97.64 225.15,97 225.01,96.34 224.65,95.8 224.09,95.42 223.45,95.3 217.55,95.3 216.89,95.44 216.35,95.8 215.97,96.36 215.85,97 215.99,97.66 216.35,98.2 216.91,98.58 217.55,98.7 223.45,98.7
SIGN362 on BOTTOM (solid shape): 224.11,103.56 224.65,103.2 225.03,102.64 225.15,102 225.01,101.34 224.65,100.8 224.09,100.42 223.45,100.3 217.55,100.3 216.89,100.44 216.35,100.8 215.97,101.36 215.85,102 215.99,102.66 216.35,103.2 216.91,103.58 217.55,103.7 223.45,103.7
SIGN362 on BOTTOM (solid shape): 224.11,98.56 224.65,98.2 225.03,97.64 225.15,97 225.01,96.34 224.65,95.8 224.09,95.42 223.45,95.3 217.55,95.3 216.89,95.44 216.35,95.8 215.97,96.36 215.85,97 215.99,97.66 216.35,98.2 216.91,98.58 217.55,98.7 223.45,98.7
SIGN362 on TOP: 243.02,84.05 234.83,84.05 234.28,84.11 233.75,84.28 233.47,84.44 233.21,84.64 233.2,84.65 231.19,86.66 231.14,86.72 231.1,86.87 231.1,90.4 230.74,90.76 230.6,90.84 230.53,90.85 226.42,90.85 226.27,90.81 226.21,90.76 225.39,89.94 225.33,89.89 225.18,89.85 218.52,89.85 218.45,89.86 218.31,89.94 216.29,91.96 216.26,92 216.25,92.06 216.25,93.36 216.25,103.4 216.29,103.55 216.4,103.66 216.55,103.7 224.9,103.7 225.05,103.66 225.16,103.55 225.2,103.4 225.2,99.54 226.34,98.4 249.22,98.4 249.28,98.39 249.32,98.36 250.19,97.49 250.22,97.45 250.23,97.39 250.23,82.94 250.22,82.88 250.19,82.84 249.59,82.24 249.55,82.21 249.49,82.2 244.93,82.2 244.87,82.21 244.83,82.24 ; 2 cut-outs
SIGN362 on BOTTOM: 215.88,103.04 215.92,103.15 216.03,103.19 220.61,103.19 220.69,103.19 220.75,103.17 225.01,103.17 225.12,103.13 225.16,103.02 225.16,100.22 226.28,99.1 229.5,99.1 229.56,99.08 229.6,99.05 230.82,97.84 248.81,97.84 248.87,97.82 248.91,97.79 249.97,96.74 250,96.69 250.01,96.63 250.01,84.24 250,84.18 249.97,84.14 247.52,81.69 247.48,81.66 247.42,81.65 244.56,81.65 244.5,81.66 244.46,81.69 241.97,84.18 235.21,84.18 235.15,84.19 235.11,84.22 231.95,87.38 231.92,87.42 231.91,87.48 231.91,90.64 228.89,93.66 226.39,93.66 226.33,93.67 226.28,93.7 225.19,94.8 216.03,94.8 215.92,94.84 215.88,94.95 ; 2 cut-outs
VREF_PFC on BOTTOM: 150.43,10.28 150.12,10.57 150.43,10.88 150.56,10.88 150.86,11.02 152.44,12.6 152.38,12.84 152.38,12.89 152.38,13.03 152.44,13.18 152.6,13.25 152.78,13.25 152.83,13.24 153.15,13.18 153.51,13.18 153.75,13.41 153.75,13.45 153.68,13.78 153.68,13.81 153.74,13.93 153.87,13.95 153.9,13.94 153.93,13.95 154.06,13.93 154.12,13.81 154.12,13.78 154.05,13.45 154.05,13.35 154.04,13.29 153.68,12.92 153.64,12.89 153.61,12.88 153.57,12.88 153.15,12.88 152.83,12.81 152.81,12.8 152.73,12.48 151.16,10.89 151.16,10.47 151.14,10.41 151.11,10.37 151.06,10.32 151.02,10.29 150.96,10.28
VREF_PFC on BOTTOM: 149.68,1.43 149.59,1.44 149.52,1.49 149.14,1.87 149.14,2.18 149.46,2.18 149.77,1.88 150.35,1.88 150.5,2.02 150.5,2.16 150.35,2.31 150.32,2.36 150.31,2.42 150.31,2.45 150.11,2.98 150.1,3.05 150.1,3.23 150.11,3.3 150.31,3.8 150.31,3.84 150.15,4.2 150.13,4.26 150.12,4.33 150.12,4.53 150.43,4.83 150.72,4.53 150.72,4.33 150.72,4.29 150.72,4.25 150.61,3.86 150.61,3.8 150.81,3.3 150.82,3.23 150.82,3.05 150.81,2.98 150.66,2.57 150.66,2.43 150.81,2.26 150.82,2.2 150.89,1.88 150.9,1.83 150.9,1.65 150.83,1.49 150.68,1.43
VREF_PFC on BOTTOM: 141.34,4.94 141.35,4.98 141.27,5.03 141.23,5.12 141.26,5.21 141.34,5.27 141.36,5.27 141.75,5.32 141.77,5.33 142.01,5.33 142.31,5.39 142.36,5.4 142.44,5.4 142.64,5.53 143.14,6.03 143.19,6.06 143.25,6.08 143.61,6.08 143.92,6.12 144.57,6.12 144.78,5.92 144.57,5.72 143.92,5.72 143.89,5.73 143.61,5.78 143.31,5.78 142.86,5.32 142.69,5.06 142.61,4.98 142.5,4.95 142.36,4.95 142.31,4.96 142.01,5.03 141.83,5.03 141.59,4.8 141.56,4.78 141.54,4.77 141.4,4.78 141.33,4.91
VREF_PFC on BOTTOM: 153.68,14.72 153.75,15.05 153.75,15.14 151.77,17.12 144.89,17.12 144.51,17.01 144.47,17 144.33,17.09 144.36,17.26 144.38,17.27 144.36,17.29 144.34,17.47 144.51,17.54 144.89,17.42 151.83,17.42 151.89,17.41 154.04,15.26 154.05,15.2 154.05,15.05 154.12,14.72 154.12,14.69 154.06,14.57 153.93,14.55 153.9,14.56 153.87,14.55 153.74,14.57 153.68,14.69
VREF_PFC on CONDUCTIVE3: 149.67,3.47 149.32,3.47 149.32,3.82 150.15,4.65 150.15,15.7 148.82,17.02 144.43,17.02 144.18,17.27 144.43,17.52 148.97,17.52 149.03,17.51 149.08,17.48 150.63,15.9 150.65,15.8 150.65,4.51 150.64,4.45 150.61,4.4

Small or netless copper shapes (teardrops, artwork), in the pictures only: 174 on TOP, 190 on BOTTOM, 1 on CONDUCTIVE2, 43 on CONDUCTIVE3, 19 on CONDUCTIVE4, 1 on CONDUCTIVE5

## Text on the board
Ref Des/Silkscreen Bottom: 1 | 2 | 6 | 7 | 3 | 4 | 5
Ref Des/Silkscreen Top: A | C | 2 | 1 | 6 | 7 | 3 | 4 | 5 | G | S
SYMBOL-1-TOP: A | C | 2 | 1 | 6 | 7 | 3 | 4 | 5 | G | S
SYMBOL-2-TOP: A | C | 2 | 1 | 4 | 3 | 7 | 6 | 5 | S | G | R225 | R74 | HS3 | TP43 | VCC12R0-1 | C7 | HS1 | TP82 | C80 | D31 | TP3 | C1 | SW | PFCOUT | HS2 | TP45 | PN | HS4 | R224 | IC80 | C803 | C804 | C800 | T4 | R805 | T8 | SNB1 | T6-5 | T6-6 | T6-3 | T5-3 | C816 | R209 | R208 | R70 | R65 | R63 | IC82 | TP83 | R815 | TP46 | OUTC2 | OUTA2 | TP42 | CN8 | CN10 | LGND | TP32 | COMP | CN7 | CN9 | HS-2-S | TP33 | C2 | R50 | R181 | R52 | R180 | R51 | R53 | R182 | R207 | R55 | R58 | R184 | C79 | FOR CONTINUED PROTECTION AGAINST RISK OF FIRE. | RV1 | C30 | F1 | L11 | C78 | C65 | C33 | C32 | C52 | IC20 | D48 | C70 | C54 | C53 | R111 | R110 | R138 | C37 | D33 | R173 | C82 | C83 | R121 | T3 | R87 | L12 | C63 | TP2 | R28 | CSA | R133 | R132 | D3 | R109 | C64 | Q1 | D9 | D8 | R222 | CSB | TP1 | R73 | Q1-G | TP4 | D38 | D39 | T2 | Q5-G | TP13 | D1 | GDB | TP6 | C87 | IC2 | C81 | C55 | Q2 | GDA | C86 | TP5 | Q3-G | TP11 | C62 | D43 | D24 | D42 | Q3 | R114 | TP9 | VINAC | TP7 | D23 | OUTC1 | D41 | Q4-G | TP12 | R126 | Q2-G | Q6-G | TP14 | VSENSE | IC4 | TP8 | D25 | TP15 | D45 | D44 | D2 | TP44 | R115 | R33 | R134 | R135 | Q4 | D36 | D37 | D30 | R72 | R71 | R108 | C101 | TP27 | TP21 | TP29 | TP17 | TP18 | Q11-G | TP30 | Q26 | Q27 | IC7 | C61 | C60 | C91 | Q7 | C88 | C89 | D29 | R25 | C90 | R125 | L5 | IC6 | Q12 | Q11 | L6 | VCC12R0-2 | Q26-G | TP22 | TP24 | OUTF | TP19 | Q7-G | R77 | TP23 | OUTE | CS | R106 | CN6 | Q19 | Q18 | TP41 | Q17 | C4 | C6 | C5 | Q16 | C3 | Q15 | R83 | R803 | R804 | R223 | R814 | C817 | R813 | C818 | OUTD2 | OUTB2 | TP37 | TP35 | TP36 | TP34 | OR-G | 12VOUT | CN1 | C31 | L1 | TP39 | R86 | TP38 | D32 | OUTA1 | FB2 | L2 | R220 | Q5 | R127 | OUTD1 | R31 | R123 | TP10 | IC5 | C57 | C18 | Q6 | R113 | R112 | D40 | FB1 | R221 | C58 | L3 | C84 | C85 | C35 | R122 | R82 | R172 | T6 | T5 | R124 | Q13 | Q27-G | TP20 | TP28 | TP31 | REPLACE ONLY WITH SAME TYPE | 250V T15AH | CAUTION
